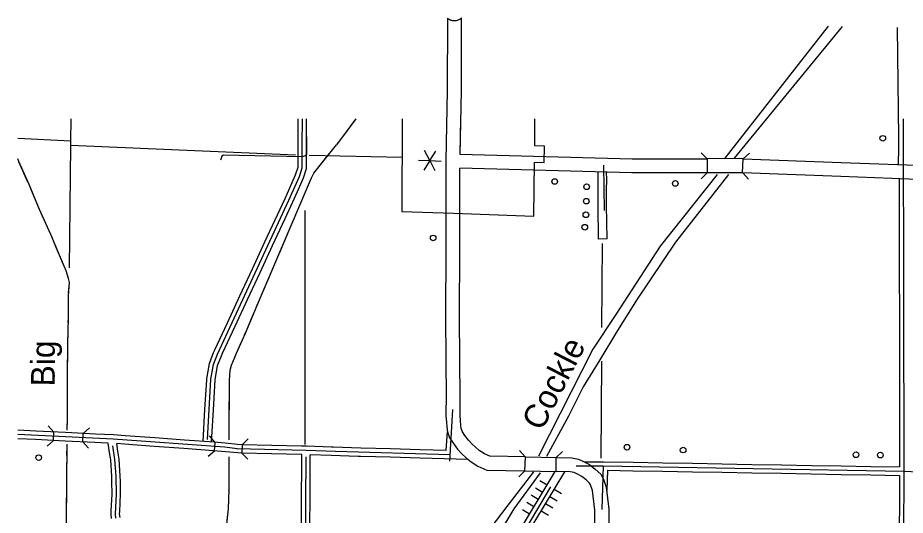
# Model space of a CAD drawing. Extents: x -4306 to 3843, y 131 to 8341.
# Drawn here: x -2796 to -274, y 6927 to 8341 of the extents above; entities that cross this region are included whole.
import ezdxf

# ---------------------------------------------------------------- set-up
doc = ezdxf.new("R2010")
doc.units = 0
for name, color, linetype in [('10', 7, 'Continuous'), ('32', 7, 'Continuous'), ('38', 7, 'Continuous'), ('4', 7, 'Continuous'), ('45', 7, 'Continuous'), ('46', 7, 'Continuous'), ('52', 7, 'Continuous'), ('53', 7, 'Continuous'), ('56', 7, 'Continuous'), ('57', 7, 'Continuous'), ('61', 7, 'Continuous'), ('62', 7, 'Continuous'), ('63', 7, 'Continuous')]:
    doc.layers.add(name, color=color, linetype=linetype)

msp = doc.modelspace()

# ---------------------------------------------------------------- linework, layer by layer
at = {"layer": '10'}
for p, q in [((-1539.2, 7953), (-1537, 8053)), ((-837.1, 7940), (-837, 7900)), ((-746.1, 7940.2), (-836.3, 7940)), ((-734.1, 7939.8), (-746.1, 7940.2)), ((-736.1, 7899.8), (-734.1, 7939.8)), ((-734.1, 7939.8), (-455.6, 7929.7)), ((-455.6, 7929.7), (-87, 7915.2)), ((-746.8, 7900.2), (-837.2, 7900)), ((-736.1, 7899.8), (-746.8, 7900.2)), ((-457.2, 7889.8), (-736.1, 7899.8)), ((-88, 7875.2), (-457.2, 7889.8)), ((-1355, 7053.1), (-1353.5, 7093.1)), ((-1353.5, 7093.1), (-1265.3, 7091.2)), ((-1266.1, 7051.2), (-1265.5, 7091.2)), ((-1265.5, 7091.2), (-1221.5, 7090.2)), ((-1221.5, 7090.2), (-1202.6, 7086.2)), ((-1202.6, 7086.2), (-1185.9, 7078.7)), ((-1185.9, 7078.7), (-1171, 7070.8)), ((-1171, 7070.8), (-1154.7, 7058)), ((-1355, 7053.1), (-1266.1, 7051.2)), ((-1226.2, 7050.3), (-1266.1, 7051.2)), ((-1215.1, 7048), (-1226.2, 7050.3)), ((-1203.4, 7042.7), (-1215.1, 7048)), ((-1192.9, 7037.2), (-1203.4, 7042.7)), ((-1180.9, 7027.7), (-1192.9, 7037.2)), ((-1154.7, 7058), (-1139.3, 7043.4)), ((-1139.3, 7043.4), (-1131.8, 7029.9)), ((-1171.2, 7018.6), (-1180.9, 7027.7)), ((-1168.3, 7013.3), (-1171.2, 7018.6)), ((-1162.7, 6997.6), (-1168.3, 7013.3)), ((-1131.8, 7029.9), (-1123.4, 7006.8)), ((-1156.2, 6941.8), (-1162.7, 6997.6)), ((-1123.4, 7006.8), (-1116.2, 6944.1)), ((-1154.7, 6376.4), (-1156.2, 6941.8)), ((-1116.2, 6944.1), (-1114.6, 6374.8))]:
    msp.add_line(p, q, dxfattribs=at)
for points in [[(-1574.7, 8338.9), (-1575.3, 8133.4), (-1579.6, 7933.8), (-1579.9, 7691.3), (-1580.5, 7484.2), (-1579.8, 7377.2), (-1579, 7253.4), (-1579.2, 7227.1), (-1579.2, 7209.6), (-1577.9, 7191.8), (-1576.8, 7177.9), (-1574.4, 7164.4), (-1569, 7146.9), (-1558.1, 7130.8), (-1546.3, 7114.5), (-1534.4, 7101.7), (-1521.6, 7089.8), (-1507.6, 7078.8), (-1488.3, 7066.4), (-1462.6, 7055.5), (-1355, 7053.3)], [(-1534.7, 8340.5), (-1536.2, 8339.1), (-1537.4, 8337.9), (-1539.1, 8336.7), (-1541, 8335.4), (-1542.7, 8334.4), (-1545, 8333.4), (-1547.2, 8332.6), (-1549.9, 8331.9), (-1552.2, 8331.6), (-1554.6, 8331.4), (-1556.1, 8331.4), (-1557.9, 8331.5), (-1560.2, 8331.8), (-1562.6, 8332.3), (-1564.7, 8333), (-1567.3, 8333.9), (-1569.8, 8335.1), (-1572.3, 8336.9), (-1574.7, 8338.9)], [(-1539.2, 7953), (-1535.3, 8132.9), (-1534.7, 8340.5)], [(-1539.4, 7953.1), (-1050.4, 7939.7), (-836.3, 7940)], [(-1353.5, 7093.3), (-1454.1, 7095.3), (-1469.6, 7101.9), (-1484.4, 7111.4), (-1495.6, 7120.2), (-1506, 7130), (-1515.4, 7140), (-1525.3, 7153.7), (-1532.5, 7164.3), (-1535.5, 7173.9), (-1537.1, 7183), (-1538, 7194.8), (-1539.2, 7211.1), (-1539.2, 7227), (-1539, 7253.3), (-1539.8, 7377.4), (-1540.5, 7484.2), (-1539.9, 7691.2), (-1539.6, 7913)], [(-837.2, 7900), (-1051, 7899.7), (-1540, 7913.1)], [(-1355, 7053.1), (-1353.5, 7093.1)]]:
    msp.add_lwpolyline(points, dxfattribs=at)
at = {"layer": '32'}
for p, q in [((-296.5, 8312.7), (-293.1, 7999.3)), ((-1976, 8053), (-1975.2, 7952.9)), ((-279.5, 8053), (-277.8, 7052)), ((-293.1, 7999.3), (-292.8, 7972.3)), ((-292.8, 7972.3), (-294.2, 7923.4)), ((-2215.8, 7947.6), (-2220.1, 7936.1)), ((-2211.3, 7950.1), (-2215.8, 7947.6)), ((-1987.8, 7945.7), (-2211.3, 7950.1)), ((-1978.8, 7948.5), (-1987.8, 7945.7)), ((-1975.2, 7952.9), (-1978.8, 7948.5)), ((-1128.2, 7793.2), (-1130.9, 7921.9)), ((-1146.4, 7880.6), (-1146.5, 7902.3)), ((-1122.4, 7880.7), (-1122.5, 7901.6)), ((-1146.6, 7852.2), (-1146.4, 7879.7)), ((-1146.4, 7879.7), (-1146.4, 7880.6)), ((-1122.6, 7852.1), (-1122.4, 7879.6)), ((-1122.4, 7879.6), (-1122.4, 7880.7)), ((-291.2, 7883.2), (-291.1, 7851.3)), ((-1146.6, 7807.4), (-1146.6, 7852.2)), ((-1122.6, 7807.5), (-1122.6, 7852.1)), ((-291.1, 7851.3), (-291, 7766.8)), ((-1145.2, 7711.5), (-1146.6, 7807.4)), ((-1121.2, 7711.9), (-1122.6, 7807.5)), ((-291, 7766.8), (-290.9, 7682.3)), ((-1121.2, 7711.9), (-1145.2, 7711.5)), ((-290.9, 7682.3), (-290.7, 7597.8)), ((-290.7, 7597.8), (-290.6, 7513.4)), ((-290.6, 7513.4), (-290.4, 7428.9)), ((-290.4, 7428.9), (-290.3, 7344.4)), ((-290.3, 7344.4), (-290.1, 7259.9)), ((-290.1, 7259.9), (-290, 7175.4)), ((-1568.5, 7080.3), (-1559.2, 7227)), ((-2744.4, 7165.9), (-2796.1, 7168.4)), ((-2660, 7161.8), (-2744.4, 7165.9)), ((-2694.7, 7139.5), (-2693.6, 7163.4)), ((-1578.6, 7111.3), (-1575.2, 7165.3)), ((-290, 7175.4), (-289.9, 7090.9)), ((-2524.5, 7143.3), (-2796.1, 7156.4)), ((-2745.6, 7141.9), (-2796.1, 7144.4)), ((-2661.2, 7137.9), (-2745.6, 7141.9)), ((-2575.6, 7157.8), (-2660, 7161.8)), ((-2611, 7135.4), (-2609.8, 7159.4)), ((-2523.8, 7155.3), (-2575.6, 7157.8)), ((-2207.5, 7120), (-2524.5, 7143.3)), ((-2491, 7152.9), (-2523.8, 7155.3)), ((-2406.7, 7146.7), (-2491, 7152.9)), ((-2322.5, 7140.5), (-2406.7, 7146.7)), ((-2238.2, 7134.3), (-2322.5, 7140.5)), ((-2576.8, 7133.8), (-2661.2, 7137.9)), ((-2538.9, 7132), (-2576.8, 7133.8)), ((-2520, 7085.4), (-2525.7, 7124.6)), ((-2492.7, 7128.9), (-2514.4, 7130.5)), ((-2408.5, 7122.7), (-2492.7, 7128.9)), ((-2324.2, 7116.5), (-2408.5, 7122.7)), ((-2239.9, 7110.4), (-2324.2, 7116.5)), ((-2206.3, 7131.9), (-2238.2, 7134.3)), ((-2237, 7110.1), (-2235.2, 7134.1)), ((-2172.2, 7115.7), (-2207.5, 7120)), ((-2171.4, 7127.6), (-2206.3, 7131.9)), ((-1976, 7111.3), (-2174.1, 7115.7)), ((-2158.4, 7127.4), (-2171.4, 7127.6)), ((-2158.4, 7127.4), (-2158.9, 7103.4)), ((-2073.9, 7125.5), (-2158.4, 7127.4)), ((-1989.5, 7123.6), (-2073.9, 7125.5)), ((-1975.6, 7123.3), (-1989.5, 7123.6)), ((-1904.8, 7120.4), (-1975.6, 7123.3)), ((-1899.3, 7120.2), (-1904.8, 7120.4)), ((-1821, 7118), (-1899.3, 7120.2)), ((-1736.6, 7115.6), (-1821, 7118)), ((-1652.1, 7113.3), (-1736.6, 7115.6)), ((-1578.6, 7111.3), (-1652.1, 7113.3)), ((-2158.9, 7103.4), (-2239.9, 7110.4)), ((-2074.5, 7101.5), (-2158.9, 7103.4)), ((-1990, 7099.6), (-2074.5, 7101.5)), ((-1988.6, 7099.6), (-1990, 7099.6)), ((-1988.8, 7064.5), (-1988.6, 7099.6)), ((-1892.6, 7107.9), (-1976, 7111.3)), ((-1964.8, 7064.4), (-1964.6, 7098.8)), ((-1905.8, 7096.4), (-1964.6, 7098.8)), ((-1828.6, 7094.2), (-1905.8, 7096.4)), ((-1568, 7099), (-1892.8, 7108)), ((-1821.7, 7094), (-1828.6, 7094.2)), ((-1737.2, 7091.6), (-1821.7, 7094)), ((-1652.8, 7089.3), (-1737.2, 7091.6)), ((-1516.2, 7085.5), (-1652.8, 7089.3)), ((-289.9, 7090.9), (-289.8, 7064.2)), ((-2516.8, 7037.1), (-2520, 7085.4)), ((-1989.4, 6980), (-1988.8, 7064.5)), ((-1965.4, 6979.9), (-1964.8, 7064.4)), ((-1208.9, 7067.1), (-1132, 7067)), ((-1186.6, 7079.1), (-1132, 7079)), ((-1132, 7067), (-1136.2, 6943)), ((-1132, 7067), (-277.8, 7052)), ((-1131.8, 7079), (-1047.3, 7077.5)), ((-1047.3, 7077.5), (-962.9, 7076)), ((-962.9, 7076), (-878.4, 7074.6)), ((-878.4, 7074.6), (-793.9, 7073.1)), ((-793.9, 7073.1), (-709.4, 7071.6)), ((-709.4, 7071.6), (-625, 7070.1)), ((-625, 7070.1), (-540.5, 7068.6)), ((-540.5, 7068.6), (-456, 7067.1)), ((-456, 7067.1), (-371.5, 7065.7)), ((-371.5, 7065.7), (-289.8, 7064.2)), ((-2515.7, 6986.7), (-2516.8, 7037.1)), ((-1120.4, 7054.8), (-1122.4, 6997.5)), ((-1120.4, 7054.8), (-1047.8, 7053.5)), ((-1047.8, 7053.5), (-963.3, 7052)), ((-963.3, 7052), (-878.8, 7050.6)), ((-878.8, 7050.6), (-794.3, 7049.1)), ((-794.3, 7049.1), (-709.9, 7047.6)), ((-709.9, 7047.6), (-625.4, 7046.1)), ((-625.4, 7046.1), (-540.9, 7044.6)), ((-540.9, 7044.6), (-456.4, 7043.1)), ((-456.4, 7043.1), (-372, 7041.7)), ((-372, 7041.7), (-289.9, 7040.2)), ((-289.9, 7040.2), (-290.4, 6967.6)), ((-277.8, 7052), (-283.5, 6198.8)), ((-277.8, 7052), (484, 7017.2)), ((-2518.6, 6930.6), (-2515.7, 6986.7)), ((-1281.6, 7007.3), (-1466.4, 6700.5)), ((-1990, 6895.6), (-1989.4, 6980)), ((-1966, 6895.4), (-1965.4, 6979.9)), ((-290.4, 6967.6), (-290.9, 6883.1)), ((-2517.4, 6919), (-2518.6, 6930.6))]:
    msp.add_line(p, q, dxfattribs=at)
msp.add_lwpolyline([(-1983.6, 6071.9), (-1976.6, 7092.7)], dxfattribs=at)
at = {"layer": '38'}
for p, q in [((-2694.2, 7151.5), (-2694.2, 7151.5)), ((-2610.4, 7147.4), (-2610.4, 7147.4)), ((-2141.1, 7143.9), (-2158.4, 7127.4)), ((-2236.1, 7122.1), (-2236.1, 7122.1)), ((-2158.9, 7103.4), (-2142.4, 7086))]:
    msp.add_line(p, q, dxfattribs=at)
for points in [[(-2693.6, 7163.4), (-2709.7, 7181.2)], [(-2592.1, 7175.5), (-2609.8, 7159.4)], [(-2712.5, 7123.3), (-2694.7, 7139.5)], [(-2235.2, 7134), (-2250.9, 7152.2)], [(-2611, 7135.4), (-2594.9, 7117.7)], [(-2255.1, 7094.4), (-2237, 7110.1)]]:
    msp.add_lwpolyline(points, dxfattribs=at)
at = {"layer": '4'}
for p, q in [((-2645, 7989.6), (-2644.4, 8053)), ((-2648.9, 7629.7), (-2645.1, 7977.8)), ((-2645.1, 7977.8), (-2645, 7989.6))]:
    msp.add_line(p, q, dxfattribs=at)
at = {"layer": '45'}
for p, q in [((-1999.4, 8016.5), (-1999.3, 8053)), ((-1987.6, 7979.9), (-1987.3, 8053)), ((-1975.4, 8016.3), (-1975.3, 8053)), ((-1999.6, 7979.9), (-1999.4, 8016.5)), ((-1975.6, 7979.9), (-1975.4, 8016.3)), ((-1999.5, 7931.9), (-1999.6, 7979.9)), ((-1987.4, 7914.3), (-1987.6, 7979.9)), ((-1975.5, 7931.9), (-1975.6, 7979.9)), ((-1999.4, 7916.2), (-1999.5, 7931.9)), ((-1975.4, 7912.4), (-1975.5, 7931.9)), ((-2006.6, 7893.8), (-1999.4, 7916.2)), ((-1995.4, 7889.5), (-1987.4, 7914.3)), ((-1984.1, 7885.2), (-1975.4, 7912.4)), ((-2025.5, 7822), (-1995.4, 7889.5)), ((-2023, 7857.1), (-2006.6, 7893.8)), ((-2001.1, 7847.3), (-1984.1, 7885.2)), ((-2036.5, 7827), (-2023, 7857.1)), ((-2014.6, 7817.1), (-2001.1, 7847.3)), ((-2228.4, 7384.9), (-2025.5, 7822)), ((-2058.1, 7780.4), (-2036.5, 7827)), ((-2036.3, 7770.3), (-2014.6, 7817.1)), ((-2093.6, 7703.8), (-2058.1, 7780.4)), ((-2071.9, 7693.7), (-2036.3, 7770.3)), ((-2129.2, 7627.2), (-2093.6, 7703.8)), ((-2107.4, 7617.1), (-2071.9, 7693.7)), ((-2164.8, 7550.5), (-2129.2, 7627.2)), ((-2143, 7540.4), (-2107.4, 7617.1)), ((-2200.3, 7473.9), (-2164.8, 7550.5)), ((-2178.6, 7463.8), (-2143, 7540.4)), ((-2235.9, 7397.3), (-2200.3, 7473.9)), ((-2214.1, 7387.2), (-2178.6, 7463.8)), ((-2239.5, 7389.6), (-2235.9, 7397.3)), ((-2251.6, 7358.4), (-2239.5, 7389.6)), ((-2240, 7355.2), (-2228.4, 7384.9)), ((-2228.3, 7352), (-2217.4, 7380.2)), ((-2217.4, 7380.2), (-2214.1, 7387.2)), ((-2259, 7314.9), (-2251.6, 7358.4)), ((-2247, 7313.5), (-2240, 7355.2)), ((-2235.1, 7312.1), (-2228.3, 7352)), ((-2259.2, 7311.9), (-2259, 7314.9)), ((-2264.1, 7227.6), (-2259.2, 7311.9)), ((-2257.1, 7142.5), (-2247, 7313.5)), ((-2240.1, 7226.2), (-2235.2, 7310.5)), ((-2235.2, 7310.5), (-2235.1, 7312.1)), ((-2269.5, 7136.6), (-2264.1, 7227.6)), ((-2245.5, 7134.8), (-2240.1, 7226.2)), ((-2535.1, 7105.5), (-2538.9, 7132)), ((-2511.3, 7108.9), (-2514.4, 7130.5)), ((-2532, 7084.1), (-2535.1, 7105.5)), ((-2508.1, 7086.6), (-2511.3, 7108.9)), ((-2528.7, 7036.6), (-2532, 7084.1)), ((-2504.8, 7037.7), (-2508.1, 7086.6)), ((-2504.5, 7023.3), (-2504.8, 7037.7)), ((-2528.5, 7022.8), (-2528.7, 7036.6)), ((-2527.7, 6986.9), (-2528.5, 7022.8)), ((-2503.7, 6986.5), (-2504.5, 7023.3)), ((-2530.2, 6939.3), (-2527.7, 6986.9)), ((-2506.2, 6938), (-2503.7, 6986.5)), ((-2530.6, 6930.3), (-2530.2, 6939.3)), ((-2506.6, 6930.8), (-2506.2, 6938)), ((-2529.3, 6917.4), (-2530.6, 6930.3)), ((-2505.5, 6920.6), (-2506.6, 6930.8))]:
    msp.add_line(p, q, dxfattribs=at)
at = {"layer": '46'}
for p, q in [((-1476.6, 6706.8), (-1269.2, 7051.3)), ((-1456.1, 6694.3), (-1241.5, 7050.7))]:
    msp.add_line(p, q, dxfattribs=at)
at = {"layer": '52'}
for p, q in [((-2645, 7989.6), (-2796.1, 7997.5)), ((-2007, 7950.1), (-2645.1, 7977.8)), ((-1703.8, 7943.7), (-1968.1, 7948.7)), ((-1979.5, 7128.3), (-1979.7, 7792.7)), ((-1135.9, 7460.7), (-1134.7, 7698.7)), ((-1137.9, 7089.2), (-1136.4, 7364.7))]:
    msp.add_line(p, q, dxfattribs=at)
at = {"layer": '53'}
msp.add_lwpolyline([(-1703.4, 8053), (-1704.3, 7790.4), (-1557.7, 7785.5), (-1329.1, 7776.6), (-1327.4, 7930.3), (-1299.6, 7929.2), (-1299.1, 7975.6), (-1327, 7976.7), (-1326.3, 8053)], dxfattribs=at)
at = {"layer": '56'}
for points in [[(-492.6, 8316.7), (-786.9, 7941.6)], [(-453.1, 8315.9), (-759.9, 7941.6)], [(-1835.5, 8053), (-1890.1, 7979.7)], [(-1835.8, 8052.6), (-1873.6, 8001.8)], [(-2106.1, 7545.8), (-1972.4, 7859.1), (-1960.9, 7886), (-1955, 7898.7), (-1890.1, 7979.7)], [(-1897.9, 7970), (-1890.1, 7979.7)], [(-1886.3, 7984.8), (-1890.1, 7979.7)], [(-1950.8, 7904.1), (-1911.1, 7953.5)], [(-2655.3, 7168.6), (-2654.9, 7205.3), (-2654.9, 7311.2), (-2654, 7412.9), (-2652.3, 7487.4), (-2652.3, 7550.5), (-2649.4, 7588.7), (-2651.6, 7600), (-2658.3, 7621.4), (-2677.5, 7665.7), (-2701.8, 7724.3), (-2734.6, 7796.1), (-2764, 7866.7), (-2793.1, 7931.9), (-2796.1, 7939.4)], [(-2767, 7873.5), (-2792.8, 7931.4)], [(-808, 7895.4), (-970.4, 7691.1), (-1096.7, 7496.9), (-1162, 7398.5), (-1315.8, 7095)], [(-775.7, 7895.2), (-927.1, 7702.9), (-1035.6, 7540.7), (-1091.8, 7451.6), (-1142.1, 7369), (-1189, 7292), (-1231, 7208.6), (-1293.2, 7093.9)], [(-1985.9, 7827.5), (-1972.4, 7859.1), (-1961, 7885.8)], [(-2734.4, 7795.6), (-2734.6, 7796.1), (-2758.8, 7854.1)], [(-2019.1, 7749.8), (-1994.2, 7808.1)], [(-2699.5, 7718.6), (-2701.8, 7724.3), (-2725.6, 7776.4)], [(-2052.3, 7672.1), (-2027.4, 7730.4)], [(-2679.2, 7669.9), (-2691.4, 7699.1)], [(-2666.7, 7640.8), (-2677.5, 7665.7), (-2679.2, 7669.9)], [(-2085.4, 7594.4), (-2060.5, 7652.6)], [(-2651.6, 7559.3), (-2649.4, 7588.7), (-2651.6, 7600), (-2658.3, 7621.4)], [(-2106.1, 7545.8), (-2093.7, 7574.9)], [(-2194.8, 7141.1), (-2194.8, 7192.4), (-2194.2, 7309.4), (-2192.5, 7339.1), (-2188.7, 7353.5), (-2174.4, 7387.4), (-2149.3, 7444.6), (-2109.3, 7539.1), (-2106.1, 7545.8)], [(-2118.7, 7516.9), (-2109.3, 7539.1), (-2106.1, 7545.8)], [(-2652.6, 7474.9), (-2652.3, 7487.4), (-2652.3, 7538.2)], [(-2151.7, 7439.2), (-2149.3, 7444.6), (-2126.9, 7497.5)], [(-2654.2, 7390.4), (-2654, 7412.9), (-2653.1, 7453.8)], [(-2185.2, 7361.6), (-2174.4, 7387.4), (-2160.2, 7419.8)], [(-2654.9, 7305.9), (-2654.9, 7311.2), (-2654.3, 7369.3)], [(-2194.4, 7278.4), (-2194.2, 7309.4), (-2192.5, 7339.1), (-2191.8, 7341.6)], [(-2654.9, 7221.4), (-2654.9, 7284.8)], [(-2194.8, 7193.9), (-2194.5, 7257.3)], [(-2655.3, 7168.6), (-2655, 7200.3)], [(-2194.8, 7141.1), (-2194.8, 7172.8)], [(-2656.6, 7128.8), (-2657, 7122.3), (-2657.7, 7024.7), (-2658.2, 6930), (-2659.3, 6846), (-2659.3, 6727.2), (-2660.4, 6614.7)], [(-2656.6, 7128.8), (-2657, 7122.3), (-2657.2, 7097.1)], [(-2392.7, 6038.1), (-2378.6, 6062.3), (-2369.7, 6077.6), (-2364.9, 6097), (-2348.4, 6171.8), (-2328.1, 6270.9), (-2309.3, 6363), (-2286.2, 6472.4), (-2273.5, 6535.7), (-2258.9, 6600.2), (-2235.6, 6710), (-2217.1, 6800.5), (-2203.6, 6884.4), (-2197.5, 6944.9), (-2195.7, 7000.5), (-2194.8, 7093.4)], [(-2657.3, 7076), (-2657.7, 7024.7), (-2657.7, 7012.6)], [(-2195.4, 7028.4), (-2195.1, 7060)], [(-1330.4, 7050.5), (-1406.5, 6952.3), (-1451.4, 6892.2), (-1538.8, 6762.8), (-1606.3, 6643.7), (-1713.9, 6460.4), (-1775.4, 6357), (-1861.2, 6194.6), (-1921.7, 6085.7), (-1963.4, 6016.6), (-2014.8, 5943)], [(-1877.3, 6111.1), (-1639.5, 6523.5), (-1385.4, 6945.6), (-1310.2, 7047.2)], [(-2195.9, 6996.7), (-2195.7, 7000.5), (-2195.4, 7028.4)], [(-2657.9, 6991.5), (-2658.2, 6930), (-2658.3, 6928.2)], [(-2200.8, 6912.4), (-2197.5, 6944.9), (-2196.5, 6975.6)]]:
    msp.add_lwpolyline(points, dxfattribs=at)
at = {"layer": '57'}
for centre in [(-337.7, 7998), (-1270.1, 7875.3), (-927.4, 7869.7), (-1179.3, 7860.2), (-1180.4, 7819.4), (-1181.4, 7780.7), (-1184.6, 7745.4), (-1615.5, 7714.8), (-1064.8, 7120.3), (-905.2, 7112.2), (-2736.6, 7090.7), (-413.7, 7098.9), (-344.5, 7097.9)]:
    msp.add_circle(centre, 8, dxfattribs=at)
at = {"layer": '61'}
for p, q in [((-1625.1, 7934.5), (-1639.7, 7963)), ((-1625.1, 7934.5), (-1607.8, 7961.4)), ((-1657.1, 7936.1), (-1625.1, 7934.5)), ((-1625.1, 7934.5), (-1642.4, 7907.6)), ((-1625.1, 7934.5), (-1593.1, 7933)), ((-1625.1, 7934.5), (-1610.5, 7906.1))]:
    msp.add_line(p, q, dxfattribs=at)
at = {"layer": '62'}
for p, q in [((-837, 7920), (-837, 7920)), ((-734.8, 7919.8), (-734.8, 7919.8)), ((-1248.1, 7107.8), (-1265.5, 7091.2)), ((-1354.3, 7073.1), (-1354.3, 7073.1)), ((-1265.9, 7071.2), (-1265.9, 7071.2))]:
    msp.add_line(p, q, dxfattribs=at)
for points in [[(-837.1, 7940), (-854.1, 7957)], [(-716.6, 7956.1), (-734.1, 7939.8)], [(-853.9, 7883), (-837, 7900)], [(-735.6, 7899.8), (-719.2, 7882.2)], [(-1353.9, 7093.1), (-1370.5, 7110.5)], [(-1372.1, 7036.5), (-1354.7, 7053.1)]]:
    msp.add_lwpolyline(points, dxfattribs=at)
at = {"layer": '63'}
for p, q in [((-1312.4, 7025.9), (-1291.9, 7013.5)), ((-1324.8, 7005.3), (-1304.3, 6993)), ((-1271.3, 7001.1), (-1250.8, 6988.8)), ((-1349.6, 6964.2), (-1329, 6951.8)), ((-1349.6, 6964.2), (-1329, 6951.8)), ((-1337.2, 6984.8), (-1316.7, 6972.4)), ((-1283.7, 6980.6), (-1263.1, 6968.2)), ((-1362, 6943.7), (-1341.4, 6931.3)), ((-1308.5, 6939.5), (-1287.9, 6927.1)), ((-1308.5, 6939.5), (-1287.9, 6927.1)), ((-1296.1, 6960), (-1275.5, 6947.6))]:
    msp.add_line(p, q, dxfattribs=at)

# ---------------------------------------------------------------- texts
at = {"layer": '56'}
for s, rotation, p in [('Big', 89.818, (-2690.8, 7292.9)), ('Cockle', 62.8132, (-1306.6, 7163.6))]:
    msp.add_text(s, height=67.59, rotation=rotation, dxfattribs=at).set_placement(p)

doc.saveas('drawing.dxf')
